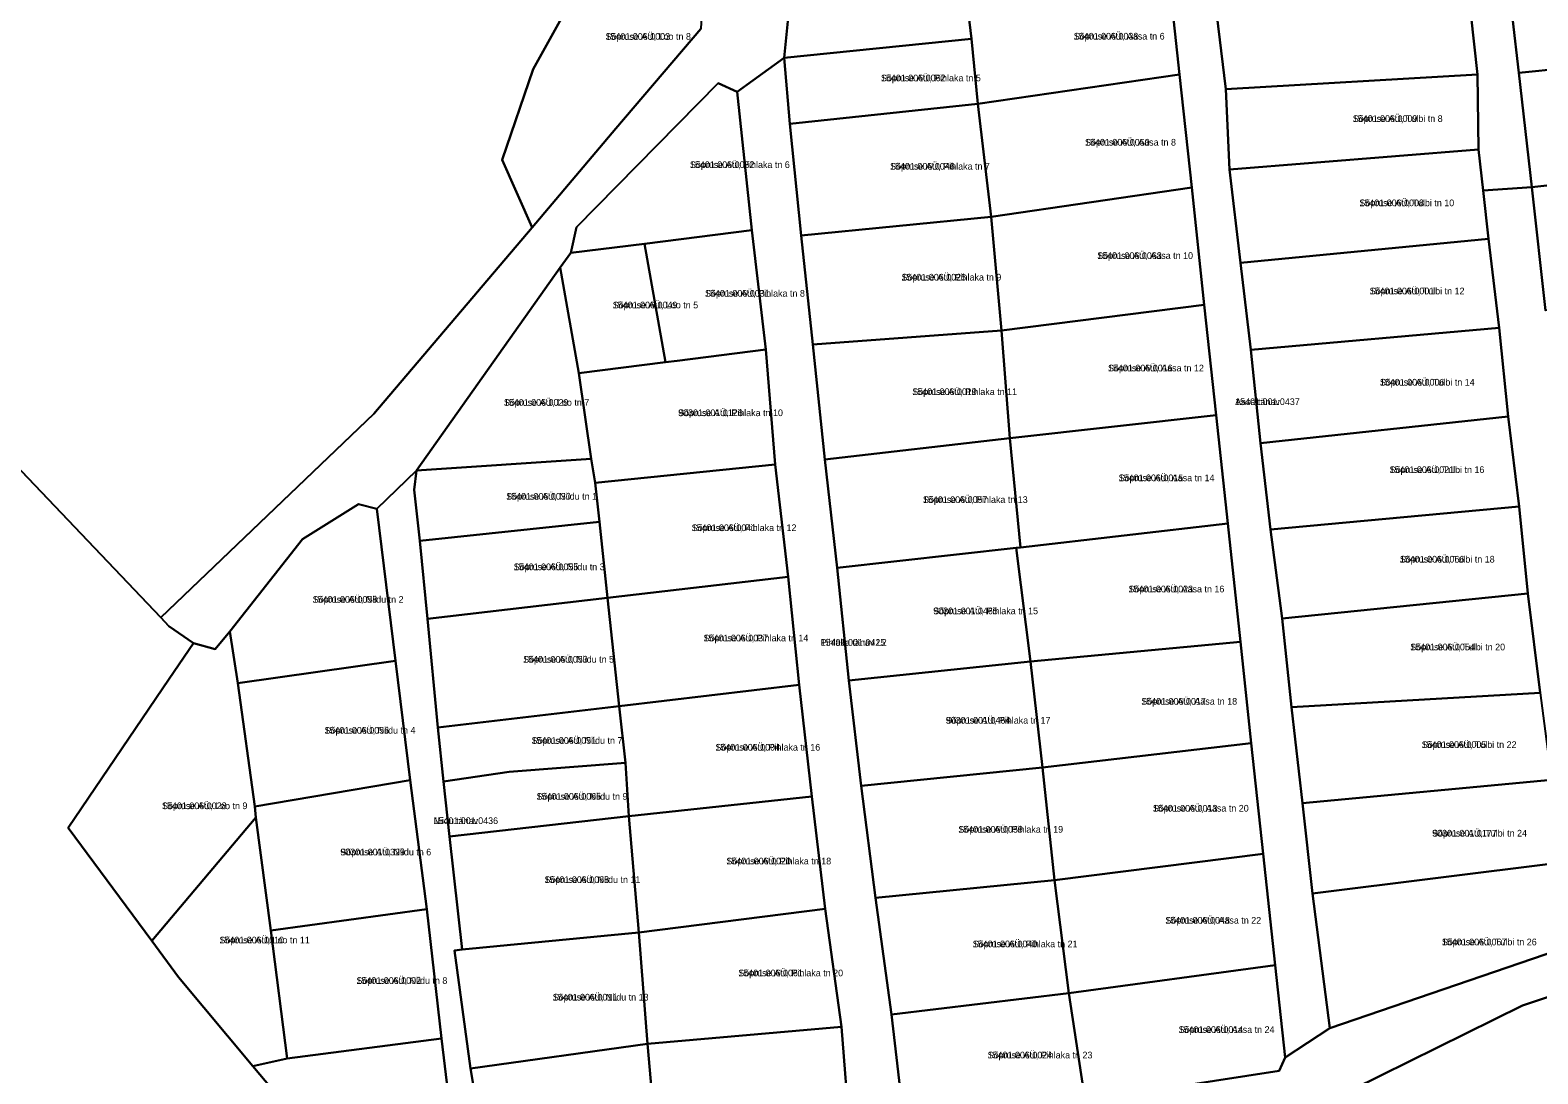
# Model space of a CAD drawing. Extents: x 634518 to 667988, y 6584667 to 6604739.
# Drawn here: x 662955.6 to 663294.1, y 6593246.7 to 6593480.9 of the extents above; entities that cross this region are included whole.
import ezdxf

# ---------------------------------------------------------------- set-up
doc = ezdxf.new("R2010")
doc.units = 0
for name, color, linetype in [('L_AADRESS', 7, 'Continuous'), ('PIIR', 7, 'Continuous'), ('TUNNUS', 7, 'Continuous')]:
    doc.layers.add(name, color=color, linetype=linetype)

msp = doc.modelspace()

# ---------------------------------------------------------------- linework, layer by layer
at = {"layer": 'PIIR'}
for points in [[(662942.12, 6593720.93), (662996.35, 6593723.15), (663060.31, 6593738.26), (663072.14, 6593752.95), (663052.3, 6593766.88), (663058.09, 6593774.85), (663073.35, 6593794.19), (663086.2, 6593810.49), (663094.98, 6593800.39), (663102.42, 6593789.23), (663105.9, 6593772.93), (663111.19, 6593748.06), (663113.31, 6593563.38), (663108.01, 6593515.2), (663094.14, 6593518.31), (663068.53, 6593472.17), (663061.55, 6593451.78), (663068.31, 6593436.61), (663032.81, 6593394.82), (662984.94, 6593349.08), (662885.24, 6593453.75)], [(663220.28, 6593498.49), (663224.04, 6593467.64), (663224.87, 6593449.65), (663227.33, 6593428.68), (663229.67, 6593409.2), (663231.86, 6593388.21), (663234.04, 6593368.83), (663236.72, 6593348.86), (663238.81, 6593328.98), (663241.26, 6593307.46), (663243.51, 6593287.2), (663247.41, 6593256.96), (663237.33, 6593250.38), (663235.09, 6593271.08), (663232.39, 6593296.04), (663229.73, 6593320.94), (663227.32, 6593343.65), (663224.49, 6593370.24), (663221.88, 6593394.55), (663219.2, 6593419.28), (663216.39, 6593445.64), (663213.68, 6593470.96), (663211.27, 6593493.24)], [(663125.91, 6593485.18), (663124.88, 6593474.7), (663114.37, 6593467.06), (663110.07, 6593469.05), (663078.27, 6593436.71), (663077.03, 6593430.91), (663074.59, 6593427.65), (663042.33, 6593382.1), (663033.46, 6593373.51), (663029.34, 6593374.51), (663016.77, 6593366.71), (663000.43, 6593345.97), (662997.15, 6593342.01), (662992.27, 6593343.38), (662986.78, 6593347.15), (662984.94, 6593349.08), (663032.81, 6593394.82), (663068.31, 6593436.61), (663087.13, 6593458.83), (663106.19, 6593481.2)], [(662885.24, 6593453.75), (662984.94, 6593349.08), (662986.78, 6593347.15), (662992.27, 6593343.38), (662986.85, 6593335.32), (662964.13, 6593301.91), (662982.9, 6593276.53), (662988.91, 6593268.4), (663005.64, 6593248.42), (663015.48, 6593236.64), (663034.4, 6593214.04), (663036.35, 6593211.79), (662641.65, 6593117.71)], [(663294.58, 6593332.19), (663291.86, 6593354.5), (663289.89, 6593374.02), (663287.44, 6593394.24), (663285.38, 6593414.11), (663283, 6593434.08), (663281.81, 6593444.95), (663292.72, 6593445.68), (663295.8, 6593418.01)]]:
    msp.add_lwpolyline(points, dxfattribs=at)
for points in [[(663265.61, 6593735.03), (663271.3, 6593730.99), (663274.02, 6593616.16), (663276.57, 6593592.3), (663279.38, 6593568.24), (663281.89, 6593544.35), (663284.45, 6593519.85), (663287, 6593495.93), (663289.83, 6593471.35), (663292.72, 6593445.68), (663281.81, 6593444.95), (663280.8, 6593454.14), (663280.56, 6593471), (663277.61, 6593497.59), (663271.07, 6593568.43), (663267.89, 6593611.85), (663267.01, 6593621.68), (663261.89, 6593681.25), (663260.49, 6593707.97), (663262.35, 6593723.45)], [(663068.53, 6593472.17), (663094.14, 6593518.31), (663108.01, 6593515.2), (663106.19, 6593481.2), (663087.13, 6593458.83), (663068.31, 6593436.61), (663061.55, 6593451.78)], [(663165.91, 6593487.79), (663166.96, 6593478.98), (663124.88, 6593474.7), (663125.91, 6593485.18), (663161.28, 6593514.98)], [(663328.84, 6593500.33), (663331.44, 6593475.5), (663289.83, 6593471.35), (663287, 6593495.93)], [(663224.04, 6593467.64), (663220.28, 6593498.49), (663277.61, 6593497.59), (663280.56, 6593471)], [(663165.91, 6593487.79), (663211.27, 6593493.24), (663213.68, 6593470.96), (663168.39, 6593464.38), (663166.96, 6593478.98)], [(663124.88, 6593474.7), (663166.96, 6593478.98), (663168.39, 6593464.38), (663126.17, 6593459.9)], [(663114.37, 6593467.06), (663124.88, 6593474.7), (663126.17, 6593459.9), (663128.72, 6593434.86), (663131.36, 6593410.4), (663134, 6593384.55), (663136.76, 6593360.24), (663139.41, 6593334.94), (663142.15, 6593311.32), (663145.42, 6593286.17), (663148.96, 6593260.03), (663151.82, 6593235.53), (663139.66, 6593233.48), (663137.73, 6593257.26), (663134.09, 6593283.74), (663131.09, 6593308.96), (663128.29, 6593333.98), (663125.76, 6593358.26), (663122.89, 6593383.46), (663120.76, 6593409.28), (663117.61, 6593436.02)], [(663331.44, 6593475.5), (663334.36, 6593450.29), (663292.72, 6593445.68), (663289.83, 6593471.35)], [(663110.07, 6593469.05), (663114.37, 6593467.06), (663117.61, 6593436.02), (663093.51, 6593432.93), (663077.03, 6593430.91), (663078.27, 6593436.71)], [(663168.39, 6593464.38), (663213.68, 6593470.96), (663216.39, 6593445.64), (663171.36, 6593439.06)], [(663224.04, 6593467.64), (663280.56, 6593471), (663280.8, 6593454.14), (663224.87, 6593449.65)], [(663126.17, 6593459.9), (663168.39, 6593464.38), (663171.36, 6593439.06), (663128.72, 6593434.86)], [(663280.8, 6593454.14), (663281.81, 6593444.95), (663283, 6593434.08), (663227.33, 6593428.68), (663224.87, 6593449.65)], [(663334.36, 6593450.29), (663337.26, 6593422.12), (663295.8, 6593418.01), (663292.72, 6593445.68)], [(663171.36, 6593439.06), (663216.39, 6593445.64), (663219.2, 6593419.28), (663173.67, 6593413.51)], [(663128.72, 6593434.86), (663171.36, 6593439.06), (663173.67, 6593413.51), (663131.36, 6593410.4)], [(663093.51, 6593432.93), (663117.61, 6593436.02), (663120.76, 6593409.28), (663100.85, 6593406.74), (663098.23, 6593406.41)], [(663077.03, 6593430.91), (663093.51, 6593432.93), (663098.23, 6593406.41), (663078.77, 6593403.94), (663074.59, 6593427.65)], [(663283, 6593434.08), (663285.38, 6593414.11), (663229.67, 6593409.2), (663227.33, 6593428.68)], [(663074.59, 6593427.65), (663078.77, 6593403.94), (663081.6, 6593384.74), (663042.33, 6593382.1)], [(663173.67, 6593413.51), (663219.2, 6593419.28), (663221.88, 6593394.55), (663175.53, 6593389.39)], [(663131.36, 6593410.4), (663173.67, 6593413.51), (663175.53, 6593389.39), (663134, 6593384.55)], [(663285.38, 6593414.11), (663287.44, 6593394.24), (663231.86, 6593388.21), (663229.67, 6593409.2)], [(663081.6, 6593384.74), (663078.77, 6593403.94), (663098.23, 6593406.41), (663100.85, 6593406.74), (663120.76, 6593409.28), (663122.89, 6593383.46), (663082.49, 6593379.33)], [(663175.53, 6593389.39), (663221.88, 6593394.55), (663224.49, 6593370.24), (663177.95, 6593364.84)], [(663231.86, 6593388.21), (663287.44, 6593394.24), (663289.89, 6593374.02), (663234.04, 6593368.83)], [(663134, 6593384.55), (663175.53, 6593389.39), (663177.95, 6593364.84), (663176.97, 6593364.73), (663136.76, 6593360.24)], [(663042.33, 6593382.1), (663081.6, 6593384.74), (663082.49, 6593379.33), (663083.42, 6593370.61), (663043.11, 6593366.34), (663041.82, 6593377.78)], [(663033.46, 6593373.51), (663042.33, 6593382.1), (663041.82, 6593377.78), (663043.11, 6593366.34), (663044.84, 6593348.84), (663047.15, 6593324.41), (663048.38, 6593312.29), (663049.73, 6593299.94), (663052.57, 6593274.58), (663050.91, 6593274.38), (663054.5, 6593247.87), (663058.85, 6593222.49), (663051.92, 6593221.69), (663048, 6593254.65), (663044.64, 6593283.63), (663040.9, 6593312.58), (663037.65, 6593339.37)], [(663082.49, 6593379.33), (663122.89, 6593383.46), (663125.76, 6593358.26), (663085.25, 6593353.53), (663083.42, 6593370.61)], [(663029.34, 6593374.51), (663033.46, 6593373.51), (663037.65, 6593339.37), (663002.24, 6593334.34), (663000.43, 6593345.97), (663016.77, 6593366.71)], [(663234.04, 6593368.83), (663289.89, 6593374.02), (663291.86, 6593354.5), (663236.72, 6593348.86)], [(663043.11, 6593366.34), (663083.42, 6593370.61), (663085.25, 6593353.53), (663044.84, 6593348.84)], [(663177.95, 6593364.84), (663224.49, 6593370.24), (663227.32, 6593343.65), (663180.23, 6593339.27), (663176.97, 6593364.73)], [(663136.76, 6593360.24), (663176.97, 6593364.73), (663180.23, 6593339.27), (663139.41, 6593334.94)], [(663085.25, 6593353.53), (663125.76, 6593358.26), (663128.29, 6593333.98), (663087.86, 6593329.24)], [(663236.72, 6593348.86), (663291.86, 6593354.5), (663294.58, 6593332.19), (663238.81, 6593328.98)], [(663044.84, 6593348.84), (663085.25, 6593353.53), (663087.86, 6593329.24), (663047.15, 6593324.41)], [(663000.43, 6593345.97), (663002.24, 6593334.34), (663006.04, 6593306.72), (663006.31, 6593304.23), (662982.9, 6593276.53), (662964.13, 6593301.91), (662986.85, 6593335.32), (662992.27, 6593343.38), (662997.15, 6593342.01)], [(663180.23, 6593339.27), (663227.32, 6593343.65), (663229.73, 6593320.94), (663182.88, 6593315.46)], [(663002.24, 6593334.34), (663037.65, 6593339.37), (663040.9, 6593312.58), (663006.04, 6593306.72)], [(663180.23, 6593339.27), (663182.88, 6593315.46), (663142.15, 6593311.32), (663139.41, 6593334.94)], [(663128.29, 6593333.98), (663131.09, 6593308.96), (663090.01, 6593304.49), (663089.3, 6593316.48), (663087.86, 6593329.24)], [(663238.81, 6593328.98), (663294.58, 6593332.19), (663297.12, 6593312.69), (663241.26, 6593307.46)], [(663047.15, 6593324.41), (663087.86, 6593329.24), (663089.3, 6593316.48), (663063.15, 6593314.48), (663048.38, 6593312.29)], [(663182.88, 6593315.46), (663229.73, 6593320.94), (663232.39, 6593296.04), (663185.6, 6593290.16)], [(663048.38, 6593312.29), (663063.15, 6593314.48), (663089.3, 6593316.48), (663090.01, 6593304.49), (663049.73, 6593299.94)], [(663142.15, 6593311.32), (663182.88, 6593315.46), (663185.6, 6593290.16), (663145.42, 6593286.17)], [(663006.04, 6593306.72), (663040.9, 6593312.58), (663044.64, 6593283.63), (663009.62, 6593278.86), (663006.31, 6593304.23)], [(663241.26, 6593307.46), (663297.12, 6593312.69), (663299.31, 6593294.15), (663243.51, 6593287.2)], [(663090.01, 6593304.49), (663131.09, 6593308.96), (663134.09, 6593283.74), (663092.23, 6593278.43)], [(663006.31, 6593304.23), (663009.62, 6593278.86), (663013.31, 6593250.15), (663005.64, 6593248.42), (662988.91, 6593268.4), (662982.9, 6593276.53)], [(663049.73, 6593299.94), (663090.01, 6593304.49), (663092.23, 6593278.43), (663052.57, 6593274.58)], [(663185.6, 6593290.16), (663232.39, 6593296.04), (663235.09, 6593271.08), (663188.82, 6593264.79)], [(663243.51, 6593287.2), (663299.31, 6593294.15), (663301.52, 6593276.65), (663298.58, 6593274.43), (663247.41, 6593256.96)], [(663145.42, 6593286.17), (663185.6, 6593290.16), (663188.82, 6593264.79), (663148.96, 6593260.03)], [(663044.64, 6593283.63), (663048, 6593254.65), (663013.31, 6593250.15), (663009.62, 6593278.86)], [(663092.23, 6593278.43), (663134.09, 6593283.74), (663137.73, 6593257.26), (663094.19, 6593253.44)], [(663092.23, 6593278.43), (663094.19, 6593253.44), (663054.5, 6593247.87), (663050.91, 6593274.38), (663052.57, 6593274.58)], [(663051.92, 6593221.69), (663058.85, 6593222.49), (663096.51, 6593227.16), (663139.66, 6593233.48), (663151.82, 6593235.53), (663192.45, 6593240.67), (663236.02, 6593247.4), (663237.33, 6593250.38), (663247.41, 6593256.96), (663298.58, 6593274.43), (663301.52, 6593276.65), (663306, 6593266.08), (663304.39, 6593265.7), (663298.27, 6593264.58), (663290.65, 6593262), (663252.5, 6593243.18), (663243.54, 6593239.44), (663242.91, 6593239.18), (663215.16, 6593233.28), (663102.17, 6593217.97), (663087.61, 6593215.97), (663065.09, 6593212.94), (663053.47, 6593211.36), (663052.77, 6593215.74)], [(663188.82, 6593264.79), (663235.09, 6593271.08), (663237.33, 6593250.38), (663236.02, 6593247.4), (663192.45, 6593240.67)], [(663307.64, 6593259.58), (663314.76, 6593167.62), (663325.51, 6593162.57), (663353.9, 6593149.24), (663341.95, 6593101.12), (663283.08, 6593101.01), (663025.91, 6593100.09), (663077.08, 6593196.44), (663087.61, 6593215.97), (663102.17, 6593217.97), (663215.16, 6593233.28), (663242.91, 6593239.18), (663243.54, 6593239.44), (663252.5, 6593243.18), (663290.65, 6593262), (663298.27, 6593264.58), (663304.39, 6593265.7), (663306, 6593266.08)], [(663148.96, 6593260.03), (663188.82, 6593264.79), (663192.45, 6593240.67), (663151.82, 6593235.53)], [(663094.19, 6593253.44), (663137.73, 6593257.26), (663139.66, 6593233.48), (663096.51, 6593227.16)], [(663005.64, 6593248.42), (663013.31, 6593250.15), (663048, 6593254.65), (663051.92, 6593221.69), (663052.77, 6593215.74), (663036.35, 6593211.79), (663034.4, 6593214.04), (663015.48, 6593236.64)], [(663054.5, 6593247.87), (663094.19, 6593253.44), (663096.51, 6593227.16), (663058.85, 6593222.49)]]:
    msp.add_lwpolyline(points, close=True, dxfattribs=at)

# ---------------------------------------------------------------- texts
at = {"layer": 'L_AADRESS'}
for s, p in [('Sõpruse AÜ, Loo tn 8', (663084.78, 6593478.75)), ('Sõpruse AÜ, Aasa tn 6', (663189.9, 6593478.81)), ('Sõpruse AÜ, Pihlaka tn 5', (663146.62, 6593469.44)), ('Sõpruse AÜ, Tulbi tn 8', (663252.54, 6593460.32)), ('Sõpruse AÜ, Aasa tn 8', (663192.44, 6593455.01)), ('Sõpruse AÜ, Pihlaka tn 6', (663103.74, 6593449.98)), ('Sõpruse AÜ, Pihlaka tn 7', (663148.67, 6593449.62)), ('Sõpruse AÜ, Tulbi tn 10', (663254.02, 6593441.41)), ('Sõpruse AÜ, Aasa tn 10', (663195.16, 6593429.58)), ('Sõpruse AÜ, Pihlaka tn 9', (663151.23, 6593424.73)), ('Sõpruse AÜ, Pihlaka tn 8', (663107.13, 6593421.11)), ('Sõpruse AÜ, Tulbi tn 12', (663256.33, 6593421.64)), ('Sõpruse AÜ, Loo tn 5', (663086.41, 6593418.48)), ('Sõpruse AÜ, Aasa tn 12', (663197.6, 6593404.34)), ('Sõpruse AÜ, Tulbi tn 14', (663258.62, 6593401.16)), ('Sõpruse AÜ, Loo tn 7', (663061.96, 6593396.62)), ('Sõpruse AÜ, Pihlaka tn 11', (663153.65, 6593399.03)), ('Aasa tänav', (663226.14, 6593396.78)), ('Sõpruse AÜ, Pihlaka tn 10', (663101.09, 6593394.3)), ('Sõpruse AÜ, Aasa tn 14', (663199.98, 6593379.7)), ('Sõpruse AÜ, Tulbi tn 16', (663260.8, 6593381.53)), ('Sõpruse AÜ, Niidu tn 1', (663062.48, 6593375.54)), ('Sõpruse AÜ, Pihlaka tn 13', (663156.04, 6593374.82)), ('Sõpruse AÜ, Pihlaka tn 12', (663104.12, 6593368.5)), ('Sõpruse AÜ, Niidu tn 3', (663064.18, 6593359.73)), ('Sõpruse AÜ, Tulbi tn 18', (663263.1, 6593361.44)), ('Sõpruse AÜ, Niidu tn 2', (663019.04, 6593352.42)), ('Sõpruse AÜ, Aasa tn 16', (663202.19, 6593354.75)), ('Sõpruse AÜ, Pihlaka tn 15', (663158.36, 6593349.84)), ('Sõpruse AÜ, Pihlaka tn 14', (663106.79, 6593343.75)), ('Pihlaka tänav L2', (663133.09, 6593342.76)), ('Sõpruse AÜ, Niidu tn 5', (663066.29, 6593338.97)), ('Sõpruse AÜ, Tulbi tn 20', (663265.44, 6593341.74)), ('Sõpruse AÜ, Aasa tn 18', (663205.06, 6593329.55)), ('Sõpruse AÜ, Pihlaka tn 17', (663161.16, 6593325.29)), ('Sõpruse AÜ, Niidu tn 4', (663021.71, 6593323.04)), ('Sõpruse AÜ, Niidu tn 7', (663068.17, 6593320.76)), ('Sõpruse AÜ, Pihlaka tn 16', (663109.46, 6593319.24)), ('Sõpruse AÜ, Tulbi tn 22', (663268.02, 6593319.83)), ('Sõpruse AÜ, Niidu tn 9', (663069.31, 6593308.21)), ('Sõpruse AÜ, Loo tn 9', (662985.22, 6593306.1)), ('Sõpruse AÜ, Aasa tn 20', (663207.66, 6593305.55)), ('Niidu tänav', (663046.16, 6593302.75)), ('Sõpruse AÜ, Pihlaka tn 19', (663163.99, 6593300.82)), ('Sõpruse AÜ, Tulbi tn 24', (663270.36, 6593299.95)), ('Sõpruse AÜ, Niidu tn 6', (663025.25, 6593295.72)), ('Sõpruse AÜ, Pihlaka tn 18', (663111.92, 6593293.7)), ('Sõpruse AÜ, Niidu tn 11', (663071.09, 6593289.53)), ('Sõpruse AÜ, Aasa tn 22', (663210.46, 6593280.41)), ('Sõpruse AÜ, Loo tn 11', (662998.11, 6593275.97)), ('Sõpruse AÜ, Pihlaka tn 21', (663167.22, 6593275.1)), ('Sõpruse AÜ, Tulbi tn 26', (663272.54, 6593275.55)), ('Sõpruse AÜ, Pihlaka tn 20', (663114.59, 6593268.59)), ('Sõpruse AÜ, Niidu tn 8', (663028.87, 6593266.89)), ('Sõpruse AÜ, Niidu tn 13', (663072.93, 6593263.15)), ('Sõpruse AÜ, Aasa tn 24', (663213.45, 6593255.88)), ('Sõpruse AÜ, Pihlaka tn 23', (663170.57, 6593250.16))]:
    msp.add_text(s, height=1.5, dxfattribs=at).set_placement(p)
at = {"layer": 'TUNNUS'}
for s, p in [('15401:006:0003', (663084.78, 6593478.75)), ('15401:006:0038', (663189.9, 6593478.81)), ('15401:006:0062', (663146.62, 6593469.44)), ('15401:006:0009', (663252.54, 6593460.32)), ('15401:006:0050', (663192.44, 6593455.01)), ('15401:006:0052', (663103.74, 6593449.98)), ('15401:006:0046', (663148.67, 6593449.62)), ('15401:006:0008', (663254.02, 6593441.41)), ('15401:006:0063', (663195.16, 6593429.58)), ('15401:006:0025', (663151.23, 6593424.73)), ('15401:006:0031', (663107.13, 6593421.11)), ('15401:006:0001', (663256.33, 6593421.64)), ('15401:006:0049', (663086.41, 6593418.48)), ('15401:006:0016', (663197.6, 6593404.34)), ('15401:006:0006', (663258.62, 6593401.16)), ('15401:006:0029', (663061.96, 6593396.62)), ('15401:006:0019', (663153.65, 6593399.03)), ('15401:001:0437', (663226.14, 6593396.78)), ('90301:001:0126', (663101.09, 6593394.3)), ('15401:006:0015', (663199.98, 6593379.7)), ('15401:006:0021', (663260.8, 6593381.53)), ('15401:006:0030', (663062.48, 6593375.54)), ('15401:006:0057', (663156.04, 6593374.82)), ('15401:006:0041', (663104.12, 6593368.5)), ('15401:006:0055', (663064.18, 6593359.73)), ('15401:006:0066', (663263.1, 6593361.44)), ('15401:006:0058', (663019.04, 6593352.42)), ('15401:006:0023', (663202.19, 6593354.75)), ('90301:001:0465', (663158.36, 6593349.84)), ('15401:006:0037', (663106.79, 6593343.75)), ('15401:001:0425', (663133.09, 6593342.76)), ('15401:006:0053', (663066.29, 6593338.97)), ('15401:006:0054', (663265.44, 6593341.74)), ('15401:006:0017', (663205.06, 6593329.55)), ('90301:001:0464', (663161.16, 6593325.29)), ('15401:006:0056', (663021.71, 6593323.04)), ('15401:006:0051', (663068.17, 6593320.76)), ('15401:006:0004', (663109.46, 6593319.24)), ('15401:006:0005', (663268.02, 6593319.83)), ('15401:006:0028', (662985.22, 6593306.1)), ('15401:006:0065', (663069.31, 6593308.21)), ('15401:006:0013', (663207.66, 6593305.55)), ('15401:001:0436', (663046.16, 6593302.75)), ('15401:006:0059', (663163.99, 6593300.82)), ('90301:001:0177', (663270.36, 6593299.95)), ('90301:001:0329', (663025.25, 6593295.72)), ('15401:006:0020', (663111.92, 6593293.7)), ('15401:006:0068', (663071.09, 6593289.53)), ('15401:006:0048', (663210.46, 6593280.41)), ('15401:006:0010', (662998.11, 6593275.97)), ('15401:006:0040', (663167.22, 6593275.1)), ('15401:006:0067', (663272.54, 6593275.55)), ('15401:006:0061', (663114.59, 6593268.59)), ('15401:006:0002', (663028.87, 6593266.89)), ('15401:006:0011', (663072.93, 6593263.15)), ('15401:006:0014', (663213.45, 6593255.88)), ('15401:006:0024', (663170.57, 6593250.16))]:
    msp.add_text(s, height=1.5, dxfattribs=at).set_placement(p)

doc.saveas('drawing.dxf')
